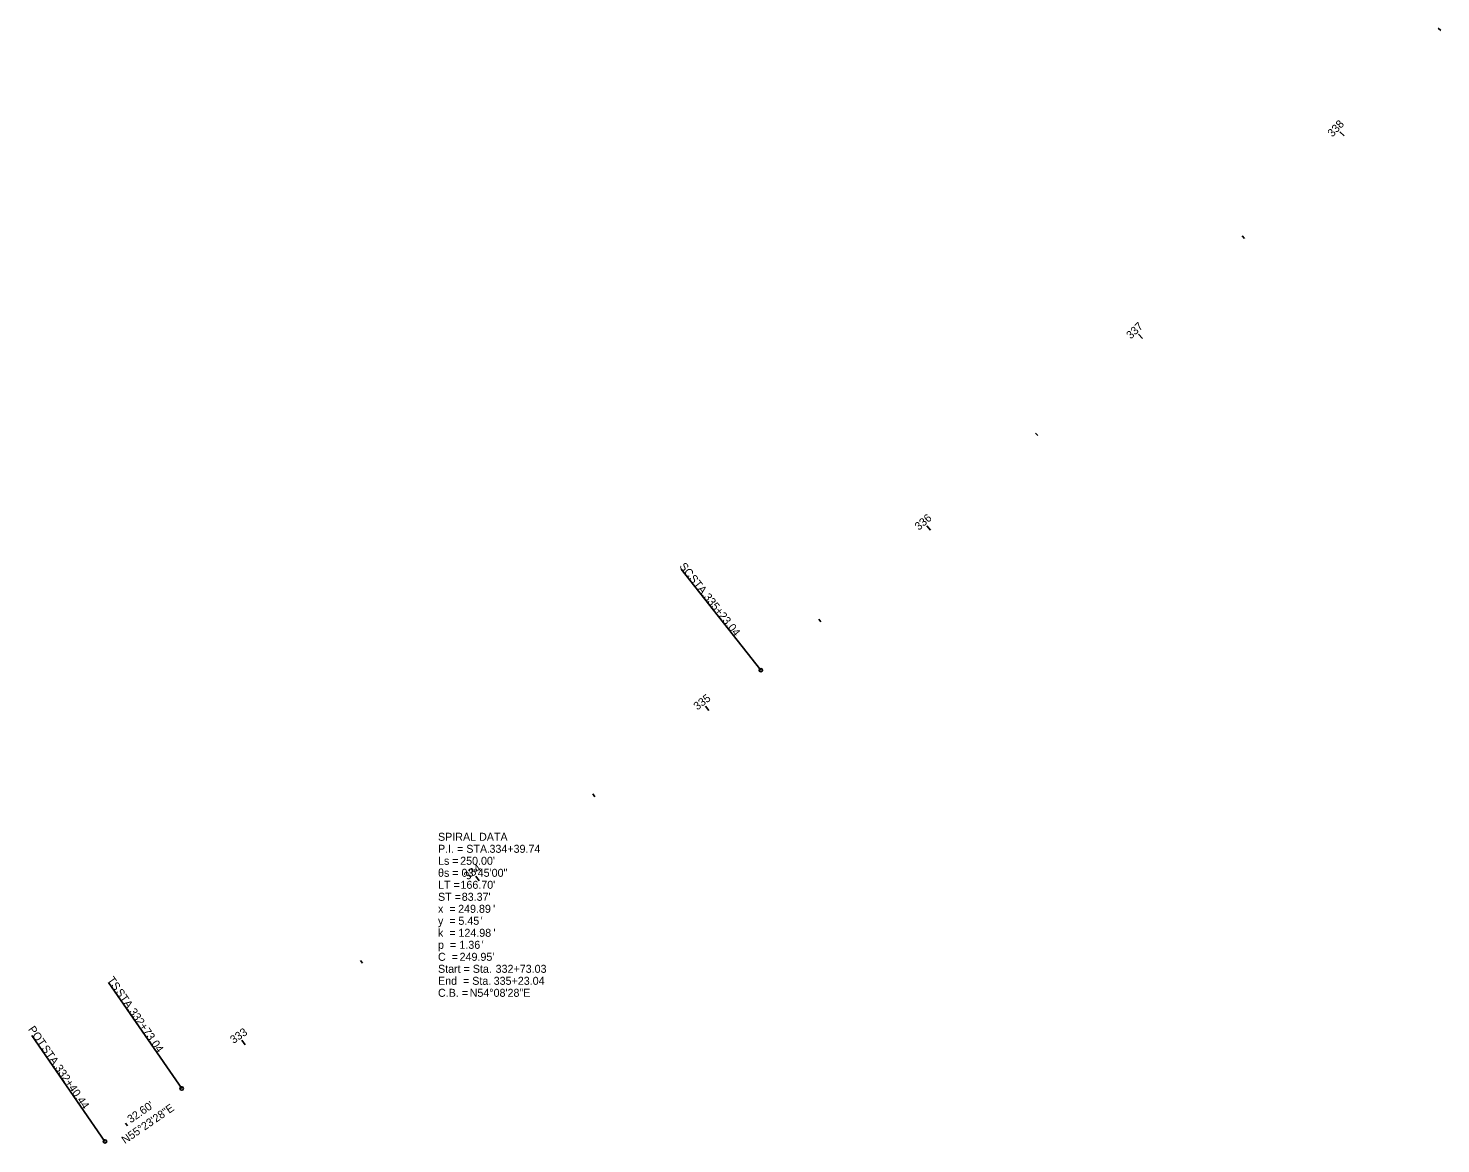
# Model space of a CAD drawing. Extents: x 1380777 to 1381940, y 503546 to 507267.
# Drawn here: x 1380776.9 to 1381270.9, y 503545.8 to 503936.2 of the extents above; entities that cross this region are included whole.
import ezdxf

# ---------------------------------------------------------------- set-up
doc = ezdxf.new("R2010")
doc.units = 0
for name, color, linetype in [('GE_X_Alignment', 7, 'Continuous'), ('GE_X_Alignment_100_Curve_Data', 7, 'Continuous'), ('GE_X_Alignment_100_Stations', 7, 'Continuous'), ('GE_X_Alignment_500_Curve_Data', 7, 'Continuous'), ('GE_X_Alignment_500_Stations', 7, 'Continuous')]:
    doc.layers.add(name, color=color, linetype=linetype)

msp = doc.modelspace()

# ---------------------------------------------------------------- linework, layer by layer
at = {"layer": 'GE_X_Alignment_100_Stations'}
for p, q in [((1381033.1, 503711.56), (1381005.17, 503746.85)), ((1380830.52, 503565.14), (1380804.96, 503602.18)), ((1380803.7, 503546.63), (1380778.14, 503583.67))]:
    msp.add_line(p, q, dxfattribs=at)
for centre in [(1381033.1, 503711.56), (1380830.52, 503565.14), (1380803.7, 503546.63)]:
    msp.add_circle(centre, 0.6, dxfattribs=at)
at = {"layer": 'GE_X_Alignment_500_Stations'}
for p, q in [((1381270.91, 503935.37), (1381270.01, 503936.17)), ((1381237.07, 503898.56), (1381235.62, 503899.93)), ((1381202.29, 503862.64), (1381201.44, 503863.49)), ((1381166.58, 503827.65), (1381165.2, 503829.09)), ((1381129.96, 503793.6), (1381129.16, 503794.49)), ((1381092.47, 503760.52), (1381091.17, 503762.04)), ((1381054.12, 503728.44), (1381053.36, 503729.37)), ((1381014.95, 503697.37), (1381013.73, 503698.95)), ((1380975.06, 503667.23), (1380974.34, 503668.2)), ((1380934.61, 503637.84), (1380933.45, 503639.46)), ((1380893.77, 503608.98), (1380893.09, 503609.97)), ((1380852.71, 503580.46), (1380851.57, 503582.1)), ((1380811.57, 503552.06), (1380810.88, 503553.05))]:
    msp.add_line(p, q, dxfattribs=at)

# ---------------------------------------------------------------- texts
at = {"layer": 'GE_X_Alignment'}
msp.add_text('N55°23\'28"E', height=2.8, rotation=34.6089, dxfattribs=at).set_placement((1380810.69, 503545.62))
at = {"layer": 'GE_X_Alignment_100_Curve_Data'}
for s, p in [('SPIRAL DATA', (1380920.18, 503651.82)), ('P.I. = STA. ', (1380920.18, 503647.62)), ('Ls = ', (1380920.18, 503643.42)), ("250.00'", (1380927.93, 503643.42)), ('334+39.74', (1380938.18, 503647.62)), ('θs = ', (1380920.18, 503639.22)), ('03°45\'00"', (1380928.4, 503639.22)), ('LT = ', (1380920.18, 503635.02)), ("166.70'", (1380928.03, 503635.02)), ('ST = ', (1380920.18, 503630.82)), ("83.37'", (1380928.48, 503630.82)), ('x  = ', (1380920.18, 503626.62)), ('249.89', (1380927.22, 503626.62)), ("'", (1380939.47, 503626.62)), ('y  = ', (1380920.18, 503622.42)), ('5.45', (1380927.32, 503622.42)), ("'", (1380935.1, 503622.42)), ('k  = ', (1380920.18, 503618.22)), ('124.98', (1380927.32, 503618.22)), ('1.36', (1380927.66, 503614.02)), ("'", (1380935.45, 503614.02)), ("'", (1380939.57, 503618.22)), ('C  = ', (1380920.18, 503609.82)), ('p  = ', (1380920.18, 503614.02)), ("249.95'", (1380927.73, 503609.82)), ('Start = Sta. ', (1380920.18, 503605.62)), ('332+73.03', (1380940.33, 503605.62)), ('End  = Sta. ', (1380920.18, 503601.42)), ('335+23.04', (1380939.65, 503601.42)), ('C.B. = ', (1380920.18, 503597.22)), ('N54°08\'28"E', (1380931.25, 503597.22))]:
    msp.add_text(s, height=2.8, dxfattribs=at).set_placement(p)
at = {"layer": 'GE_X_Alignment_100_Stations'}
for s, rotation, p in [('SC', 308.3589, (1381004.44, 503747.83)), (' STA. ', 308.3589, (1381007.15, 503744.41)), ('335+23.04', 308.3589, (1381012.93, 503737.1)), ('TS', 304.6089, (1380804.37, 503603.11)), (' STA. ', 304.6089, (1380806.7, 503599.73)), ('332+73.04', 304.6089, (1380812, 503592.05)), ('POT', 304.6089, (1380776.68, 503585.84)), (' STA. ', 304.6089, (1380780.73, 503579.97)), ('332+40.44', 304.6089, (1380786.03, 503572.3))]:
    msp.add_text(s, height=2.8, rotation=rotation, dxfattribs=at).set_placement(p)
at = {"layer": 'GE_X_Alignment_500_Curve_Data'}
msp.add_text("32.60'", height=2.8, rotation=34.6089, dxfattribs=at).set_placement((1380812.71, 503552.9))
at = {"layer": 'GE_X_Alignment_500_Stations'}
for s, rotation, p in [('338', 46.6677, (1381233.03, 503897.91)), ('337', 43.6677, (1381162.51, 503827.22)), ('336', 40.6677, (1381088.37, 503760.3)), ('335', 37.6995, (1381010.88, 503697.39)), ('334', 35.576, (1380930.49, 503637.96)), ('333', 34.6525, (1380848.66, 503580.7))]:
    msp.add_text(s, height=2.8, rotation=rotation, dxfattribs=at).set_placement(p)

doc.saveas('drawing.dxf')
